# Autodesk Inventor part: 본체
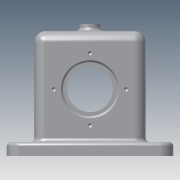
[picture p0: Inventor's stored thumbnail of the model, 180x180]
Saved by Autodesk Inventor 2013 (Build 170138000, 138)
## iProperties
Created: 2018-11
Part Number: 본체
Material: 알루미늄 6061
Document SubType Name: Modeling
Designer: Administrator
Density: 2.71 g/cm^3
Mass: 1021.68 g
Surface Area: 775.693 cm^2
Volume: 377.005 cm^3
Author: Administrator
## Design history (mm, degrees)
sketch "스케치1"
  geometry: L1 (-50, -60)-(50, -60); L2 (60, -50)-(60, 50); L3 (50, 60)-(-50, 60); L4 (-60, 50)-(-60, -50); L5 (-60, -60)-(60, 60); L6 (60, -60)-(-60, 60); L7 (-32, -40)-(32, -40); L8 (40, -32)-(40, 32); L9 (32, 40)-(-32, 40); L10 (-40, 32)-(-40, -32); L11 (-40, -40)-(40, 40); L12 (40, -40)-(-40, 40); A1 r 10 centre (-50, 50) between (-50, 60) and (-60, 50); A2 r 10 centre (-50, -50) between (-60, -50) and (-50, -60); A3 r 10 centre (50, 50) between (60, 50) and (50, 60); A4 r 10 centre (50, -50) between (50, -60) and (60, -50); A5 r 8 centre (-32, 32) between (-32, 40) and (-40, 32); A6 r 8 centre (-32, -32) between (-40, -32) and (-32, -40); A7 r 8 centre (32, -32) between (32, -40) and (40, -32); A8 r 8 centre (32, 32) between (40, 32) and (32, 40); 1 further point
  constraints: 24 end point, 16 point on circle, 16 point on line, 16 tangent, 8 centre point, 6 equal radius, 4 midpoint, 4 parallel, 2 horizontal, 2 perpendicular
  dimensions: "d0" = 120 distance of L6.end L5.end; "d1" = 120 distance of L5.end L6.start; "d2" = 80 distance of L11.end L12.end; "d3" = 80 distance of L12.start L11.end; "d4" = 10 radius of A1; "d5" = 8 radius of A5
extrude "돌출1" new body sketch "스케치1" distance "d6" = 10; taper "d7" = 0 deg
extrude "돌출2" join sketch "스케치1" distance "d8" = 90; taper "d9" = 0 deg
sketch "스케치2"
  geometry: L1 (-20, -30)-(20, -30); L2 (23, -27)-(23, 27); L3 (20, 30)-(-20, 30); L4 (-23, 27)-(-23, -27); L5 (-23, -30)-(23, 30); L6 (23, -30)-(-23, 30); A1 r 3 centre (-20, 27) between (-20, 30) and (-23, 27); A2 r 3 centre (20, 27) between (23, 27) and (20, 30); A3 r 3 centre (20, -27) between (20, -30) and (23, -27); A4 r 3 centre (-20, -27) between (-23, -27) and (-20, -30); 1 further point
  constraints: 12 end point, 8 point on circle, 8 point on line, 8 tangent, 4 centre point, 3 equal radius, 2 midpoint, 2 parallel, 1 horizontal, 1 perpendicular
  dimensions: "d10" = 46 distance of L5.end L6.end; "d12" = 60 distance of L6.start L5.end; "d13" = 3 radius of A1
extrude "돌출3" cut sketch "스케치2" distance "d14" = 80; taper "d15" = 0 deg
sketch "스케치3"
  geometry: C1 r 7.5 at (0, 0); 1 further point
  constraints: 1 centre point, 1 coincident
  dimensions: "d16" = 15 diameter of C1
extrude "돌출4" join sketch "스케치3" distance "d17" = 5; taper "d18" = 0 deg
sketch "스케치4"
  geometry: L1 (10, -18)-(10, 82) reference; 3 further points
  constraints: 1 horizontal alignment, 1 midpoint
  dimensions: "d19" = 48 distance from line of L1 point (-38, 32)
hole "구멍1" sketch "스케치4" at (-38, 32) diameter "d20" = 33; stored, may be unused: countersink angle "d24" = 90 deg, drill point angle "d26" = 118 deg; dims "d21" = 6, "d22" = 40, "d23" = 14, "d25" = 8
sketch "스케치5" dims "d27" = 52
  geometry: C1 r 20 at (-38, 32) reference; 3 further points
  constraints: 2 horizontal alignment, 1 coincident, 2 other
hole "구멍2" sketch "스케치5" at (-64, 32) diameter "d29" = 3.242; stored, may be unused: countersink angle "d33" = 90 deg, drill point angle "d35" = 118 deg; dims "d30" = 8, "d31" = 40, "d32" = 14, "d34" = 10
sketch "스케치6" dims "d46" = 10, "d53" = 10, "d80" = 10
  geometry: L1 (-32, 40)-(32, 40) reference; L2 (40, 32)-(40, -32) reference; L3 (32, -40)-(-32, -40) reference; L4 (-40, -32)-(-40, 32) reference; L5 (-60, 50)-(-60, -50) reference; L6 (-50, -60)-(50, -60) reference; L7 (-40, 0)-(40, 0); L8 (0, -40)-(0, 40); L9 (50, 60)-(-50, 60) reference; C1 r 3.3 at (-50, -50); C2 r 3.3 at (-50, -25); C3 r 3.3 at (-50, 0); C4 r 3.3 at (-50, 25); C5 r 3.3 at (-50, 50); C6 r 3.3 at (-40, -50); C7 r 3.3 at (-30, -50); C8 r 3.3 at (-20, -50); C9 r 3.3 at (-10, -50); C10 r 3.3 at (0, -50); C11 r 3.3 at (10, -50); C12 r 3.3 at (20, -50); C13 r 3.3 at (30, -50); C14 r 3.3 at (40, -50); C15 r 3.3 at (50, -50); C16 r 3.3 at (30, 50); C17 r 3.3 at (40, 50); C18 r 3.3 at (20, 50); C19 r 3.3 at (10, 50); C20 r 3.3 at (0, 50); C21 r 3.3 at (-10, 50); C22 r 3.3 at (-20, 50); C23 r 3.3 at (-30, 50); C24 r 3.3 at (-40, 50); C25 r 3.3 at (50, 25); C26 r 3.3 at (50, 0); C27 r 3.3 at (50, -25); C28 r 3.3 at (50, 50); A1 r 10 centre (-50, -50) between (-60, -50) and (-50, -60) reference; 1 further point
  constraints: 28 centre point, 12 symmetric about line, 4 end point, 4 midpoint, 2 horizontal, 1 coincident, 1 vertical, 42 other
  dimensions: "d39" = 6.6 diameter of C1; "d43" = 25 distance of C1.centre C2.centre; "d50" = 10 distance of C1.centre C6.centre; "d77" = 10 distance of C17.centre C28.centre
extrude "돌출5" cut sketch "스케치6" stored distance "d55" = 5; taper "d56" = 0 deg
chamfer "모따기1" distance "d57" = 1; stored, may be unused: second distance "d58" = 2, angle "d59" = 45 deg
hole "구멍3" diameter "d62" = 4.917; stored, may be unused: countersink angle "d66" = 90 deg, drill point angle "d68" = 118 deg; dims "d60" = 10, "d61" = 10, "d63" = 8, "d64" = 40, "d65" = 14, "d67" = 10
fillet "모깎기1" dims "d69" = 3
fillet "모깎기2" dims "d70" = 0.6
fillet "모깎기3" dims "d71" = 8
sketch "스케치8"
  geometry: L1 (0, 69)-(64, 69) reference; L2 (-18, -13)-(82, -13) reference; 3 further points
  constraints: 1 midpoint, 1 vertical alignment, 1 other
  dimensions: "d72" = 48 distance from line of L2 point (32, 35)
feature "엠보싱1" sketch "스케치8" dims "d0" = 120, "d1" = 120, "d2" = 80, "d3" = 80, "d4" = 10, "d5" = 8, "d73" = 0.5, "d74" = 0
node "솔리드1"
pattern_circular "원형 패턴1" dims angle "d37" = 360 deg
mirror "대칭1"
